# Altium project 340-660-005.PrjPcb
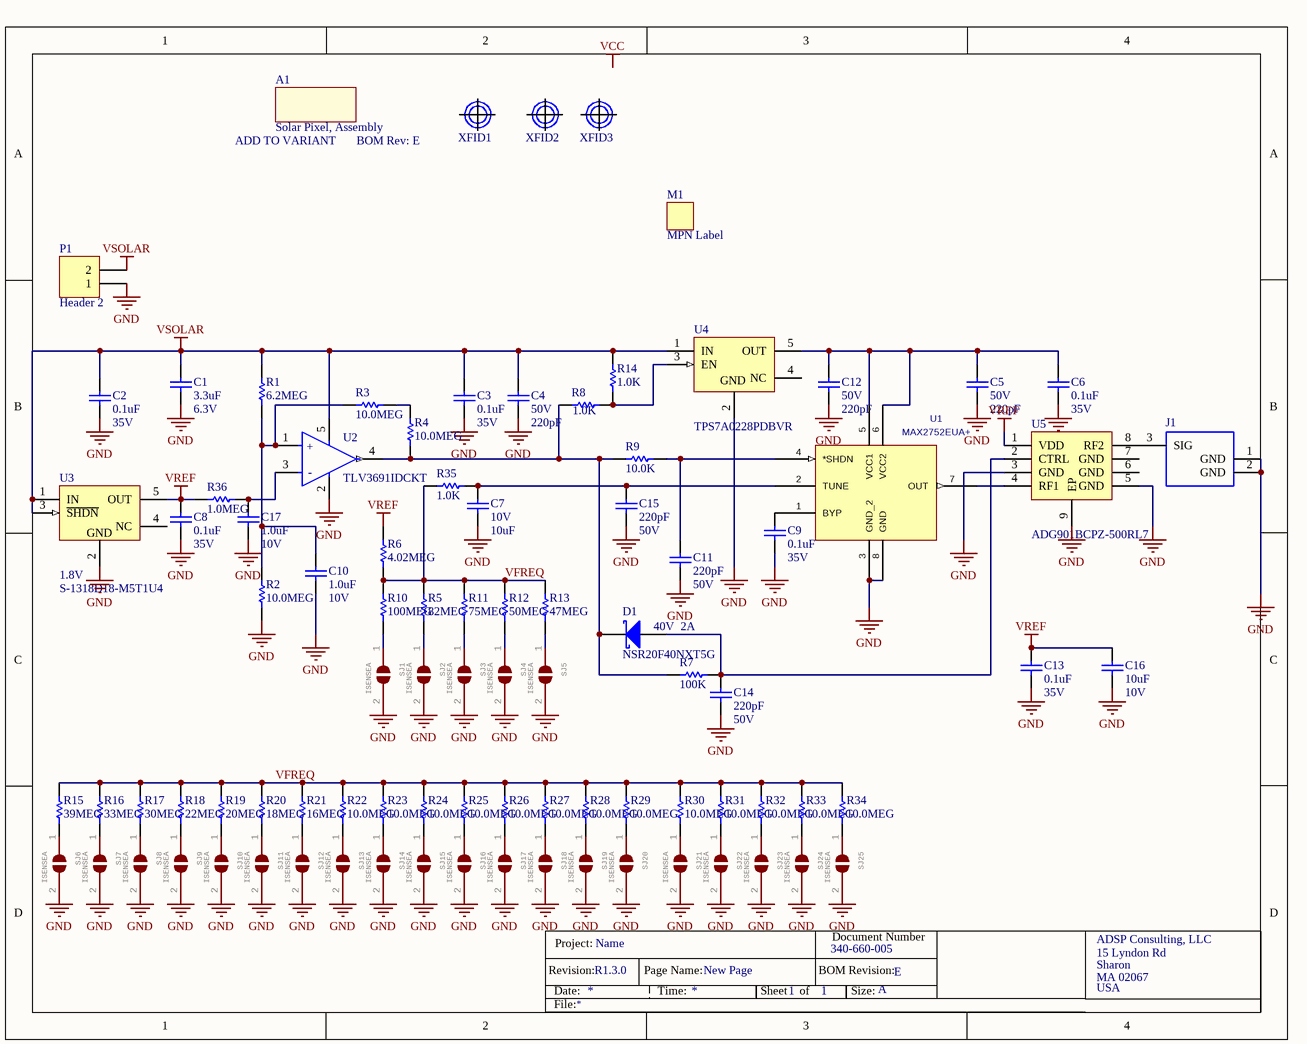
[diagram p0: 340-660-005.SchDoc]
ASSM_PN: DEPRECATED_USE_VARIANTS; Bom_Rev: E; DOC_NUM: 340-660-005; DOC_REV: R1.3.0; PCB_PN: 21000-1002; TITLE: Solar Pixel
1 sheet, 92 parts. Net scope: global (net labels, ports and power ports of the same name join across sheets).
Board file: 340-660-005.PcbDoc

## Sheet 340-660-005.SchDoc: Solar Pixel
size A; Author: M. Fridberg; CompanyName: ADSP Consulting, LLC; DrawnBy: M. Fridberg; Engineer: M. Fridberg; Organization: ADSP Consulting, LLC; Address1: 15 Lyndon Rd; Address2: Sharon; Address3: MA 02067; Address4: USA; DocumentNumber: ###-###-###-SCH; Revision: 0.0.0; SheetNumber: 1; SheetTotal: 1; Project: Name; PageName: New Page

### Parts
?  (no value)  (graphical)
A1  Solar Pixel, Assembly  BOM Rev: E  ADSP_PN: ADD TO VARIANT  (mechanical)
C1  value 3.3uF  Voltage: 6.3V  [0402CAP]  (hidden comment: C1005X5R0J335K050BC)
C2  value 0.1uF  Voltage: 35V  [0402CAP]  (hidden comment: GMK105BJ104KV-F)
C3  value 0.1uF  Voltage: 35V  [0402CAP]  (hidden comment: GMK105BJ104KV-F)
C4  value 220pF  Voltage: 50V  [0402CAP]  (hidden comment: ECJ-0EC1H221J)
C5  value 220pF  Voltage: 50V  [0402CAP]  (hidden comment: ECJ-0EC1H221J)
C6  value 0.1uF  Voltage: 35V  [0402CAP]  (hidden comment: GMK105BJ104KV-F)
C7  value 10uF  Voltage: 10V  [0402CAP]  (hidden comment: CL05A106MP5NUNC)
C8  value 0.1uF  Voltage: 35V  [0402CAP]  (hidden comment: GMK105BJ104KV-F)
C9  value 0.1uF  Voltage: 35V  [0402CAP]  (hidden comment: GMK105BJ104KV-F)
C10  value 1.0uF  Voltage: 10V  [0402CAP]  (hidden comment: 0402ZD105KAT2A)
C11  value 220pF  Voltage: 50V  [0402CAP]  (hidden comment: ECJ-0EC1H221J)
C12  value 220pF  Voltage: 50V  [0402CAP]  (hidden comment: ECJ-0EC1H221J)
C13  value 0.1uF  Voltage: 35V  [0402CAP]  (hidden comment: GMK105BJ104KV-F)
C14  value 220pF  Voltage: 50V  [0402CAP]  (hidden comment: ECJ-0EC1H221J)
C15  value 220pF  Voltage: 50V  [0402CAP]  (hidden comment: ECJ-0EC1H221J)
C16  value 10uF  Voltage: 10V  [0402CAP]  (hidden comment: CL05A106MP5NUNC)
C17  value 1.0uF  Voltage: 10V  [0402CAP]  (hidden comment: 0402ZD105KAT2A)
D1  Voltage: 40V  Current: 2A  [DIODE_2-DSN_ON]  (hidden comment: NSR20F40NXT5G)
J1  (no value)  [CONN_HRS-U.FL-R-SMT_V]
M1  MPN Label  [LABEL_7x7mm]  (no BOM)
P1  Header 2  [HDR1X2]
R1  6.2MEG  [0402RES]
R2  value 10.0MEG  [0402RES]  (hidden comment: CRCW040210M0FKED)
R3  value 10.0MEG  [0402RES]  (hidden comment: CRCW040210M0FKED)
R4  value 10.0MEG  [0402RES]  (hidden comment: CRCW040210M0FKED)
R5  value 82MEG  [0402RES]  (hidden comment: HMC0402JT82M0)
R6  4.02MEG  [0402RES]
R7  value 100K  [0402RES]  (hidden comment: RC0402FR-07100KL)
R8  value 1.0K  [0402RES]  (hidden comment: RCS04021K00FKED)
R9  value 10.0K  [0402RES]  (hidden comment: CRCW040210K0FKEDHP)
R10  value 100MEG  [0402RES]  (hidden comment: HMC0402JT100M)
R11  value 75MEG  [0402RES]  (hidden comment: HMC0402JT75M0)
R12  value 50MEG  [0402RES]  (hidden comment: HMC0402JT50M0)
R13  value 47MEG  [0402RES]  (hidden comment: HMC0402JT47M0)
R14  value 1.0K  [0402RES]  (hidden comment: RCS04021K00FKED)
R15  value 39MEG  [0402RES]  (hidden comment: HMC0402JT39M0)
R16  value 33MEG  [0402RES]  (hidden comment: HMC0402JT33M0)
R17  value 30MEG  [0402RES]  (hidden comment: HMC0402JT30M0)
R18  value 22MEG  [0402RES]  (hidden comment: RC0402JR-0722ML)
R19  value 20MEG  [0402RES]
R20  value 18MEG  [0402RES]
R21  value 16MEG  [0402RES]
R22  value 10.0MEG  [0402RES]  (hidden comment: CRCW040210M0FKED)
R23  value 10.0MEG  [0402RES]  (hidden comment: CRCW040210M0FKED)
R24  value 10.0MEG  [0402RES]  (hidden comment: CRCW040210M0FKED)
R25  value 10.0MEG  [0402RES]  (hidden comment: CRCW040210M0FKED)
R26  value 10.0MEG  [0402RES]  (hidden comment: CRCW040210M0FKED)
R27  value 10.0MEG  [0402RES]  (hidden comment: CRCW040210M0FKED)
R28  value 10.0MEG  [0402RES]  (hidden comment: CRCW040210M0FKED)
R29  value 10.0MEG  [0402RES]  (hidden comment: CRCW040210M0FKED)
R30  value 10.0MEG  [0402RES]  (hidden comment: CRCW040210M0FKED)
R31  value 10.0MEG  [0402RES]  (hidden comment: CRCW040210M0FKED)
R32  value 10.0MEG  [0402RES]  (hidden comment: CRCW040210M0FKED)
R33  value 10.0MEG  [0402RES]  (hidden comment: CRCW040210M0FKED)
R34  value 10.0MEG  [0402RES]  (hidden comment: CRCW040210M0FKED)
R35  value 1.0K  [0402RES]  (hidden comment: RCS04021K00FKED)
R36  value 1.0MEG  [0402RES]  (hidden comment: RC0402FR-071ML)
SJ1  ISENSEA  [SOLDERJUMPER_ARROW_NOPASTE]  (no BOM)
SJ2  ISENSEA  [SOLDERJUMPER_ARROW_NOPASTE]  (no BOM)
SJ3  ISENSEA  [SOLDERJUMPER_ARROW_NOPASTE]  (no BOM)
SJ4  ISENSEA  [SOLDERJUMPER_ARROW_NOPASTE]  (no BOM)
SJ5  ISENSEA  [SOLDERJUMPER_ARROW_NOPASTE]  (no BOM)
SJ6  ISENSEA  [SOLDERJUMPER_ARROW_NOPASTE]  (no BOM)
SJ7  ISENSEA  [SOLDERJUMPER_ARROW_NOPASTE]  (no BOM)
SJ8  ISENSEA  [SOLDERJUMPER_ARROW_NOPASTE]  (no BOM)
SJ9  ISENSEA  [SOLDERJUMPER_ARROW_NOPASTE]  (no BOM)
SJ10  ISENSEA  [SOLDERJUMPER_ARROW_NOPASTE]  (no BOM)
SJ11  ISENSEA  [SOLDERJUMPER_ARROW_NOPASTE]  (no BOM)
SJ12  ISENSEA  [SOLDERJUMPER_ARROW_NOPASTE]  (no BOM)
SJ13  ISENSEA  [SOLDERJUMPER_ARROW_NOPASTE]  (no BOM)
SJ14  ISENSEA  [SOLDERJUMPER_ARROW_NOPASTE]  (no BOM)
SJ15  ISENSEA  [SOLDERJUMPER_ARROW_NOPASTE]  (no BOM)
SJ16  ISENSEA  [SOLDERJUMPER_ARROW_NOPASTE]  (no BOM)
SJ17  ISENSEA  [SOLDERJUMPER_ARROW_NOPASTE]  (no BOM)
SJ18  ISENSEA  [SOLDERJUMPER_ARROW_NOPASTE]  (no BOM)
SJ19  ISENSEA  [SOLDERJUMPER_ARROW_NOPASTE]  (no BOM)
SJ20  ISENSEA  [SOLDERJUMPER_ARROW_NOPASTE]  (no BOM)
SJ21  ISENSEA  [SOLDERJUMPER_ARROW_NOPASTE]  (no BOM)
SJ22  ISENSEA  [SOLDERJUMPER_ARROW_NOPASTE]  (no BOM)
SJ23  ISENSEA  [SOLDERJUMPER_ARROW_NOPASTE]  (no BOM)
SJ24  ISENSEA  [SOLDERJUMPER_ARROW_NOPASTE]  (no BOM)
SJ25  ISENSEA  [SOLDERJUMPER_ARROW_NOPASTE]  (no BOM)
U1  MAX2752EUA+  [21-0036K_MXM]
U2  TLV3691IDCKT  [SC70/5]
U3  Vout: 1.8V  [SOT-23/5]  (hidden comment: S-1318D18-M5T1U4)
U4  TPS7A0228PDBVR  [SOT-23/5]
U5  ADG901BCPZ-500RL7  [SON50P300X300X85-9N-D]
XFID1  (no value)  [FID_TOP_BOT_39]
XFID2  (no value)  [FID_TOP_BOT_39]
XFID3  (no value)  [FID_TOP_BOT_39]

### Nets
GND: C1.1 C2.1 C3.1 C4.1 C5.1 C6.1 C7.1 C8.1 C9.1 C10.1 C11.1 C12.1 C13.1 C14.1 C15.1 C16.1 C17.1 J1.1(GND) J1.2(GND) P1.1 R2.1 SJ1.2 SJ2.2 SJ3.2 SJ4.2 SJ5.2 SJ6.2 SJ7.2 SJ8.2 SJ9.2 SJ10.2 SJ11.2 SJ12.2 SJ13.2 SJ14.2 SJ15.2 SJ16.2 SJ17.2 SJ18.2 SJ19.2 SJ20.2 SJ21.2 SJ22.2 SJ23.2 SJ24.2 SJ25.2 U1.3(GND_2) U1.8(GND) U2.2(GND) U3.2(GND) U4.2(GND) U5.3(GND) U5.5(GND) U5.9(EP)
VREF: C8.2 C13.2 C16.2 R6.2 R36.2 U3.5(OUT) U5.1(VDD)
VSOLAR: C1.2 C2.2 C3.2 C4.2 P1.2 R1.2 R14.1 U2.5(VCC) U3.1(IN) U3.3(~{SHDN}) U4.1(IN)
VFREQ: R5.2 R6.1 R10.2 R11.2 R12.2 R13.2 R15.2 R16.2 R17.2 R18.2 R19.2 R20.2 R21.2 R22.2 R23.2 R24.2 R25.2 R26.2 R27.2 R28.2 R29.2 R30.2 R31.2 R32.2 R33.2 R34.2 R35.2
NetC5_2: C5.2 C6.2 C12.2 U1.5(VCC1) U1.6(VCC2) U4.5(OUT)
NetC7_2: C7.2 C15.2 R35.1 U1.2(TUNE)
NetC9_2: C9.2 U1.1(BYP)
NetC10_2: C10.2 R1.1 R2.2 R3.2 U2.1(IN+)
NetC11_2: C11.2 R9.1 U1.4(*SHDN)
NetC14_2: C14.2 D1.A R7.1 U5.2(CTRL)
NetC17_2: C17.2 R36.1 U2.3(IN-)
NetD1_C: D1.C(K) R4.1 R7.2 R8.2 R9.2 U2.4(OUT)
NetJ1_3: J1.3(SIG) U5.8(RF2)
NetR3_1: R3.1 R4.2
NetR5_1: R5.1 SJ2.1
NetR8_1: R8.1 R14.2 U4.3(EN)
NetR10_1: R10.1 SJ1.1
NetR11_1: R11.1 SJ3.1
NetR12_1: R12.1 SJ4.1
NetR13_1: R13.1 SJ5.1
NetR15_1: R15.1 SJ6.1
NetR16_1: R16.1 SJ7.1
NetR17_1: R17.1 SJ8.1
NetR18_1: R18.1 SJ9.1
NetR19_1: R19.1 SJ10.1
NetR20_1: R20.1 SJ11.1
NetR21_1: R21.1 SJ12.1
NetR22_1: R22.1 SJ13.1
NetR23_1: R23.1 SJ14.1
NetR24_1: R24.1 SJ15.1
NetR25_1: R25.1 SJ16.1
NetR26_1: R26.1 SJ17.1
NetR27_1: R27.1 SJ18.1
NetR28_1: R28.1 SJ19.1
NetR29_1: R29.1 SJ20.1
NetR30_1: R30.1 SJ21.1
NetR31_1: R31.1 SJ22.1
NetR32_1: R32.1 SJ23.1
NetR33_1: R33.1 SJ24.1
NetR34_1: R34.1 SJ25.1
NetU1_7: U1.7(OUT) U5.4(RF1)

Not connected (* = marked no-connect by the designer): U3 4(NC); U4 4(NC); U5 6(GND) 7(GND)

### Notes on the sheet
- Labels drawn without touching a wire or pin: VCC

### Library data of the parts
? = ADSP_TitleBlock: ADSP Consulting TITLE BLOCK
A1 = PCB_Assembly: DocNum: 340-660-005
C1 = CAP_0402_10uF_X5R_10V: CAP CER 10UF 10V X5R 0402; ADSP_PN: 01020-167; Mfg: TDK; Type: CAPACITOR
C2 C3 C6 C8 C9 C13 = CAP_0402_0.1uF_X5R_35V: CAP CER .10UF 35V X5R 0402; ADSP_PN: 01010-054; Mfg: Taiyo Yuden; Type: CAPACITOR
C4 C5 C11 C12 C14 C15 = CAP_0402_220pF_NP0_50V: CAP 220PF 50V CERAMIC 0402 SMD; ADSP_PN: 01010-028; Mfg: Panasonic; Type: CAPACITOR
C7 C16 = CAP_0402_10uF_X5R_10V: CAP CER 10UF 10V X5R 0402; ADSP_PN: 01020-053; Mfg: Samsung; Type: CAPACITOR
C10 C17 = CAP_0402_1uF_X5R_10V: CAP CERAMIC 1UF 10V X5R 0402; ADSP_PN: 01020-057; Mfg: AVX; Type: CAPACITOR
D1 = Diode_SHOTTKY_NSR20F40NXT5G: Diode Schottky 40V 2A (DC) Surface Mount 2-DSN (1.6x.80); Mfg: ON Semi; ADSP_PN: 08100-027
J1 = CONN_Hirose_U.FL-R-SMT(10): Ultra Small Surface Mount Coaxial Connector, 50 Ohm, -40 to 90 degC, 3-Pin SMD, RoHS, Tape and Reel; ADSP_PN: 03000-233; Current Rating: 3 A; Mfg: Hirose
M1 = Label_MPN: Serial Number Label Placeholder
P1 = Header 2: Header, 2-Pin
R1 = Res_0402_6.2MEG_1%: RES 6.2M OHM 1/16W 1% 0402 SMD; ADSP_PN: 00100-134; Mfg: Vishay; Mfg_PN: CRCW04026M20JNED
R2-R4 R19 R22-R34 = Res_0402_10MEG_1%: RES 10M OHM 1/16W 1% 0402 SMD; ADSP_PN: 00100-135; Mfg: Vishay
R5 = Res_0402_10MEG_1%: RES 10M OHM 1/16W 1% 0402 SMD; ADSP_PN: 00100-228; Mfg: Stackpole
R6 = Res_0402_4.02MEG_1%: RES 4.02M OHM 1/16W 1% 0402 SMD; ADSP_PN: 00100-132; Mfg: Vishay; Mfg_PN: CRCW04024M02FKED
R7 = Res_0402_100K_1%: RES 100K OHM 1/16W 1% 0402 SMD; ADSP_PN: 00100-028; Mfg: Yageo
R8 R14 R35 = Res_0402_1.0K_1%: RES SMD 1K OHM 1% 1/5W 0402; ADSP_PN: 00100-158; Mfg: Panasonic
R9 = Res_0402_10.0K_1%: RES 10K OHM 1/10W 1% 0402 SMD; ADSP_PN: 00100-161; Mfg: Vishay
R10 = Res_0402_10MEG_1%: RES 10M OHM 1/16W 1% 0402 SMD; ADSP_PN: 00100-226; Mfg: Stackpole
R11 = Res_0402_10MEG_1%: RES 10M OHM 1/16W 1% 0402 SMD; ADSP_PN: 00100-232; Mfg: Stackpole
R12 = Res_0402_10MEG_1%: RES 10M OHM 1/16W 1% 0402 SMD; ADSP_PN: 00100-231; Mfg: Stackpole
R13 = Res_0402_10MEG_1%: RES 10M OHM 1/16W 1% 0402 SMD; ADSP_PN: 00100-227; Mfg: Stackpole
R15 = Res_0402_10MEG_1%: RES 10M OHM 1/16W 1% 0402 SMD; ADSP_PN: 00100-233; Mfg: Stackpole
R16 = Res_0402_10MEG_1%: RES 10M OHM 1/16W 1% 0402 SMD; ADSP_PN: 00100-230; Mfg: Stackpole
R17 = Res_0402_10MEG_1%: RES 10M OHM 1/16W 1% 0402 SMD; ADSP_PN: 00100-234; Mfg: Stackpole
R18 = Res_0402_10MEG_1%: RES 10M OHM 1/16W 1% 0402 SMD; ADSP_PN: 00100-229; Mfg: Yageo
R20 = Res_0402_10MEG_1%: RES 10M OHM 1/16W 1% 0402 SMD; ADSP_PN: 00100-135
R21 = Res_0402_10MEG_1%: RES 10M OHM 1/16W 1% 0402 SMD; ADSP_PN: 00100-
R36 = Res_0402_1MEG_1%: RES 1.0M OHM 1/16W 5% 0402 SMD; ADSP_PN: 00100-157; Mfg: Yageo
SJ1-SJ25 = SOLDERJUMPER_OPEN: SMD Solder JUMPER   Solder the two pads together to create a connection, or remove the solder to break it.REFLOW - Use this footprint for solder paste and reflow ovens. WAVE - Use this footprint for hand-soldering (larger pads).    CLOSED - Has a trace between the two pads to ensure it is closed by default.  The trace needs to be cut to disable the jumper, and can be closed again by creating a solder bridge between the two pads.; GateName_1: 1; BOM: EXCLUDE
U1 = MAX2752EUA+: RF IC VCO ISM 2.025GHz ~ 2.165GHz On-Chip Tank Circuit 8-uMAX/uSOP; Mfg: Maxim Integrated Products; ADSP_PN: 10030-015
U2 = TLV3691IDCKT: IC COMPARATOR NANO-POWER SC70-5; ADSP_PN: 07013-008; Mfg: Texas Instrument; Iq: 150nA; Vmin: 0.9V; Vmax: 5.5V; Delay: 35us
U3 = S-1318D18-M5T1U4: Ultra-Low Quescent Current Linear Voltage Regulator IC Positive Fixed 1.8V 100mA SOT-23-5; ADSP_PN: 07600-034; Mfg: ABLIC
U4 = TPS7A0228PDBVR: 2.8V, 1-µA, ultra-low-IQ, 200-mA low-dropout (LDO) regulator in a small-sized; ADSP_PN: 07600-???; Mfg: Texas Instruments
U5 = ADG901BCPZ: RF Switch IC General Purpose SPST 2.5 GHz 50Ohm 8-LFCSP (3x3); ADSP_PN: 07221-014; Mfg: CEL
XFID1-XFID3 = MOUNT_FIDUCIAL: Mounting Hole

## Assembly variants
BaseBoard: not fitted C10 D1 J1 P1 R3 R4 R8 R19 R20 R21 R23 R24 R25 R26 R27 R28 R29 R30 R31 R32 R33 R34 U4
